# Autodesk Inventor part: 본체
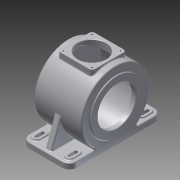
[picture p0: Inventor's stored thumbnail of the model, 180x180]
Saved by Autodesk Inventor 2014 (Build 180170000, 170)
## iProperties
Created: 2015-06
Part Number: 본체
Material: 알루미늄 6061
Document SubType Name: Modeling
Designer: SEC
Density: 2.71 g/cm^3
Appearance: 알루미늄 - 평지
Author: SEC
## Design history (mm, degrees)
sketch "스케치1"
  geometry: C1 r 85 at (0, 0); 1 further point
  constraints: 1 centre point, 1 coincident
  dimensions: "d0" = 170 diameter of C1
extrude "돌출1" new body sketch "스케치1" stored distance "d1" = 118; taper "d2" = 0 deg
node "작업 평면1"
sketch "스케치2"
  geometry: L1 (-59, 115)-(59, 115); L2 (59, 115)-(59, -115); L3 (59, -115)-(-59, -115); L4 (-59, -115)-(-59, 115); L5 (-59, 115)-(59, -115); 2 further points
  constraints: 10 end point, 2 parallel, 1 coincident, 1 horizontal, 1 midpoint, 1 perpendicular
  dimensions: "d4" = 118 distance of L1.start L1.end; "d5" = 230 distance of L1.end L2.end
extrude "돌출2" join sketch "스케치2" distance "d6" = 14; taper "d7" = 0 deg
fillet "모깎기1" dims "d8" = 18
sketch "스케치3"
  geometry: C1 r 65 at (0, 0); A1 r 85 centre (0, 0) between (-71, -46.733) and (-71, 46.733) reference
  constraints: 1 centre point, 1 coincident
  dimensions: "d9" = 130 diameter of C1
extrude "돌출3" join sketch "스케치3" distance "d10" = 13; taper "d11" = 0 deg
node "작업 평면2"
sketch "스케치4"
  geometry: L1 (-42.5, 42.5)-(42.5, 42.5); L2 (42.5, 42.5)-(42.5, -42.5); L3 (42.5, -42.5)-(-42.5, -42.5); L4 (-42.5, -42.5)-(-42.5, 42.5); L5 (-42.5, 42.5)-(42.5, -42.5); 2 further points
  constraints: 10 end point, 2 parallel, 2 perpendicular, 1 coincident, 1 horizontal, 1 midpoint
  dimensions: "d13" = 85 distance of L1.end L2.end
extrude "돌출4" join sketch "스케치4" stored distance "d14" = 13; taper "d15" = 0 deg
sketch "스케치5"
  geometry: L1 (-115, -85)-(-115, -71) reference; L2 (-97, -71)-(-46.733, -71) reference; L3 (-112, -71)-(-97, -71) reference; L4 (-109, -71)-(-84.87, -4.703); A1 r 85 centre (0, 0) between (46.733, -71) and (-46.733, -71) reference; A2 r 3 centre (-112, -74) between (-112, -71) and (-115, -74) reference; 3 further points
  constraints: 2 end point, 1 point on circle, 1 point on line
  dimensions: "d17" = 6 distance from line of L4.start L1; "d18" = 110 deg angle of L3 L4
feature "리브1" sketch "스케치5" dims "d19" = 12, "d20" = 15, "d21" = 0, "d22" = 0, "d23" = 1, "d24" = 1
sketch "스케치6"
  geometry: L1 (7.5, -109)-(-7.5, -109) reference; L2 (-50, -81)-(-50, -97); L3 (-32, -81)-(-32, -97); A1 r 9 centre (-41, -97) between (-50, -97) and (-32, -97); A2 r 9 centre (-41, -81) between (-32, -81) and (-50, -81); 1 further point
  constraints: 4 end point, 4 point on circle, 4 tangent, 2 centre point, 1 parallel, 1 perpendicular
  dimensions: "d25" = 18 distance between parallel lines of L3 L2; "d26" = 16 distance of A1.centre A2.centre; "d27" = 97 vertical distance of A1.centre point (0, 0); "d28" = 41 horizontal distance of point (0, 0) A1.centre
extrude "돌출5" join sketch "스케치6" distance "d29" = 3; taper "d30" = 0 deg
fillet "모깎기3" dims "d31" = 3
sketch "스케치7"
  geometry: C1 r 65 at (0, 0); A1 r 85 centre (0, 0) between (71, 46.733) and (71, -46.733) reference; 2 further points
  constraints: 1 centre point, 1 coincident
  dimensions: "d41" = 130 diameter of C1
extrude "돌출6" join sketch "스케치7" distance "d42" = 3; taper "d43" = 0 deg
hole "구멍1" diameter "d34" = 95; stored, may be unused: countersink angle "d38" = 90 deg, drill point angle "d40" = 0 deg; dims "d35" = 6, "d36" = 4, "d37" = 2, "d39" = 11, "d44" = 10, "d45" = 10
hole "구멍2" diameter "d48" = 154; stored, may be unused: countersink angle "d52" = 90 deg, drill point angle "d54" = 0 deg; dims "d46" = 10, "d47" = 10, "d49" = 6, "d50" = 4, "d51" = 2, "d53" = 102
sketch "스케치8"
  geometry: L1 (51, 77)-(51, -77) reference; L2 (0, 0)-(51, 0); L3 (51, 31)-(47.5, 29.368); L4 (47.5, 29.368)-(47.5, 0)
  constraints: 6 end point, 2 point on line, 1 midpoint, 1 perpendicular
  dimensions: "d55" = 115 deg angle of L3 L1; "d56" = 3.5 distance between parallel lines of L1 L4; "d57" = 62 diameter of L3.start L2
revolve "회전1" sketch "스케치8" stored, may be unused: angle "d58" = 90 deg
hole "구멍3" diameter "d61" = 30; stored, may be unused: countersink angle "d65" = 90 deg, drill point angle "d67" = 0 deg; dims "d62" = 6, "d63" = 47, "d64" = 14, "d66" = 17, "d68" = 10, "d69" = 10
sketch "스케치9"
  geometry: 1 further point
hole "구멍4" sketch "스케치9" at (0, 0) diameter "d70" = 70; stored, may be unused: countersink angle "d74" = 90 deg, drill point angle "d76" = 0 deg; dims "d71" = 6, "d72" = 47, "d73" = 14, "d75" = 50
sketch "스케치10"
  geometry: C1 r 47.5 at (0, 0) reference; 1 further point
  dimensions: "d77" = 55 distance of C1.centre point (-55, 0)
hole "구멍5" sketch "스케치10" at (-55, 0) diameter "d78" = 3.242; stored, may be unused: countersink angle "d82" = 90 deg, drill point angle "d84" = 118 deg; dims "d79" = 15, "d80" = 47, "d81" = 14, "d83" = 17
sketch "스케치11"
  geometry: L1 (-35.5, 35.5)-(35.5, 35.5); L2 (35.5, 35.5)-(35.5, -35.5); L3 (35.5, -35.5)-(-35.5, -35.5); L4 (-35.5, -35.5)-(-35.5, 35.5); L5 (-35.5, 35.5)-(35.5, -35.5); C1 r 35 at (0, 0) reference; 1 further point
  constraints: 10 end point, 2 parallel, 2 perpendicular, 1 coincident, 1 horizontal, 1 midpoint
  dimensions: "d88" = 71 distance of L1.end L2.end
hole "구멍6" sketch "스케치11" at (-35.5, 35.5), (35.5, 35.5), (35.5, -35.5), (-35.5, -35.5) diameter "d89" = 3.242; stored, may be unused: countersink angle "d93" = 90 deg, drill point angle "d95" = 118 deg; dims "d90" = 10, "d91" = 47, "d92" = 14, "d94" = 13
fillet "모깎기4" dims "d96" = 7
sketch "스케치12"
  geometry: L1 (-9, 0)-(-9, 16) reference; L2 (9, 16)-(9, 0) reference; L3 (-4, 0)-(-4, 16); L4 (4, 16)-(4, 0); A1 r 9 centre (0, 0) between (-9, 0) and (9, 0) reference; A2 r 9 centre (0, 16) between (9, 16) and (-9, 16) reference; A3 r 4 centre (0, 0) between (-4, 0) and (4, 0); A4 r 4 centre (0, 16) between (4, 16) and (-4, 16); 1 further point
  constraints: 4 end point, 4 point on circle, 2 centre point, 3 other
  dimensions: "d97" = 8 distance between parallel lines of L4 L3
extrude "돌출7" cut sketch "스케치12" stored distance "d98" = 3; taper "d99" = 0 deg
fillet "모깎기5" dims "d100" = 0.3
chamfer "모따기1" distance "d101" = 1; stored, may be unused: second distance "d102" = 2, angle "d103" = 45 deg
fillet "모깎기6" dims "d104" = 3
fillet "모깎기7" dims "d105" = 3
fillet "모깎기9" dims "d107" = 3
fillet "모깎기10" dims "d108" = 3
fillet "모깎기12" dims "d110" = 3
node "작업 평면9"
  node "작업 평면8"
sketch "스케치13"
  geometry: 2 further points
  constraints: 1 coincident, 1 other
feature "엠보싱1" sketch "스케치13" dims "d0" = 170, "d114" = 0.5, "d115" = 0
fillet "모깎기13" dims "d116" = 3
node "솔리드1"
mirror "대칭1"
mirror "대칭2"
mirror "대칭3"
pattern_circular "원형 패턴1" dims angle "d86" = 360 deg
mirror "대칭4"
mirror "대칭5"
other parameters: "d3" = -85, "d12" = -173, "d113" = 65 deg
